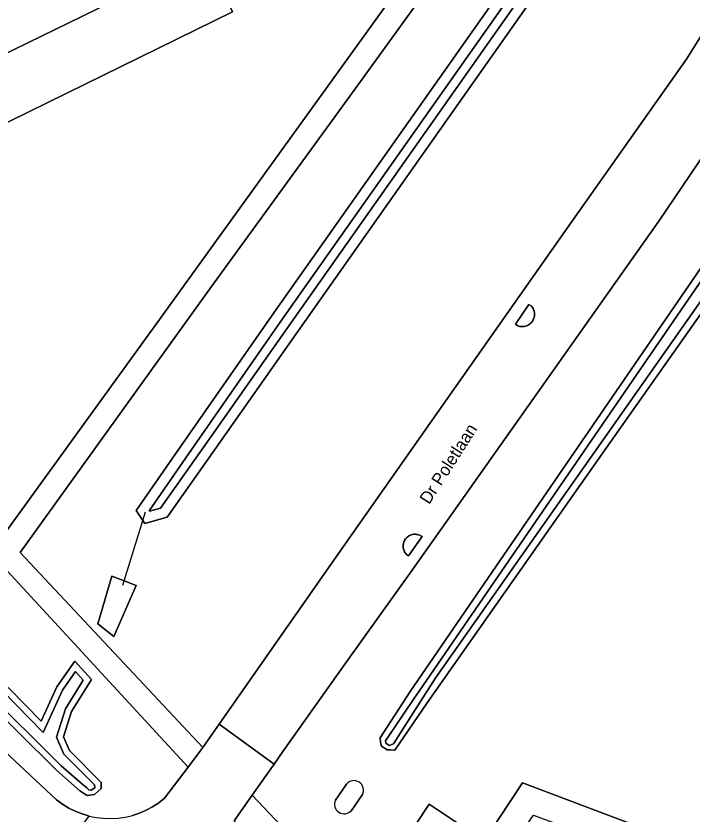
# Model space of a CAD drawing. Extents: x 158132 to 159664, y 385256 to 387218.
# Drawn here: x 159149 to 159204, y 386220.2 to 386285 of the extents above; entities that cross this region are included whole.
import ezdxf

# ---------------------------------------------------------------- set-up
doc = ezdxf.new("R2010")
doc.units = 0
for name, color, linetype in [('IMGEO_Berm_groen', 7, 'Continuous'), ('IMGEO_Duiker', 7, 'Continuous'), ('IMGEO_Groenvoorziening', 7, 'Continuous'), ('IMGEO_Oever', 7, 'Continuous'), ('IMGEO_Openbare_ruimte_label', 7, 'Continuous'), ('IMGEO_Pand', 7, 'Continuous'), ('IMGEO_Parkeervlak_open', 7, 'Continuous'), ('IMGEO_Rijbaan_lokaal_gesloten', 7, 'Continuous'), ('IMGEO_Rijbaan_lokaal_open', 7, 'Continuous'), ('IMGEO_Verkeerseiland_gesloten', 7, 'Continuous'), ('IMGEO_Voetpad_onverhard', 7, 'Continuous'), ('IMGEO_Voetpad_open', 7, 'Continuous'), ('IMGEO_Waterloop', 7, 'Continuous')]:
    doc.layers.add(name, color=color, linetype=linetype)

msp = doc.modelspace()

# ---------------------------------------------------------------- linework, layer by layer
at = {"layer": 'IMGEO_Berm_groen'}
for points in [[(159148.321, 386239.967), (159141.561, 386231.755), (159143.645, 386229.653), (159144.934, 386228.353), (159146.374, 386226.9), (159152.343, 386221.356), (159152.823, 386221.004), (159153.33, 386220.695), (159153.863, 386220.431), (159154.417, 386220.214), (159154.869, 386220.08), (159154.987, 386220.045), (159155.57, 386219.927), (159156.16, 386219.859), (159156.755, 386219.843), (159157.348, 386219.878), (159157.936, 386219.964), (159158.515, 386220.101), (159159.08, 386220.287), (159159.626, 386220.521), (159160.15, 386220.802), (159160.648, 386221.127), (159161.116, 386221.493), (159163.035, 386224.02)], [(159151.105, 386227.739), (159152.378, 386230.539), (159153.841, 386232.634), (159155.182, 386231.149), (159153.558, 386228.54), (159152.897, 386226.477), (159153.39, 386225.373), (159155.959, 386222.778), (159155.978, 386222.279), (159155.425, 386221.792), (159154.84, 386221.719), (159154.242, 386222.105), (159152.364, 386223.748), (159146.066, 386229.985), (159144.775, 386231.281), (159143.282, 386232.763), (159144.586, 386234.362), (159145.95, 386232.976), (159147.235, 386231.67)]]:
    msp.add_lwpolyline(points, close=True, dxfattribs=at)
at = {"layer": 'IMGEO_Duiker'}
msp.add_lwpolyline([(159157.726, 386238.808), (159157.834, 386239.159), (159159.345, 386244.053), (159159.564, 386244.761)], dxfattribs=at)
at = {"layer": 'IMGEO_Groenvoorziening'}
for points in [[(159108.848, 386282.056), (159117.567, 386273.343), (159130.648, 386260.403), (159140.343, 386250.704), (159148.101, 386242.94), (159161.049, 386260.864), (159173.188, 386277.68), (159184.907, 386293.934), (159196.39, 386309.759)], [(159148.09, 386301.717), (159150.98, 386295.609), (159151.929, 386296.073), (159159.646, 386299.844), (159161.883, 386295.226), (159164.449, 386289.929), (159166.651, 386285.382), (159145.544, 386275.043)], [(159189.781, 386297.34), (159177.033, 386279.71), (159164.932, 386263.075), (159149.388, 386241.446), (159164.231, 386225.621), (159165.558, 386227.517), (159175.438, 386241.635), (159184.786, 386254.949), (159194.152, 386268.251), (159203.536, 386281.54), (159205.023, 386283.901)], [(159208.814, 386279.502), (159201.285, 386268.363), (159181.095, 386239.838), (159175.909, 386232.566), (159170.744, 386225.279), (159170.034, 386224.271), (159168.243, 386221.728), (159180.772, 386208.483), (159190.199, 386222.736), (159197.505, 386219.987), (159205.272, 386217.087)], [(159197.068, 386250), (159182.45, 386229.237), (159179.829, 386225.403), (159179.44, 386225.427), (159179.21, 386225.427), (159178.75, 386225.731), (159178.657, 386226.01), (159178.628, 386226.397), (159181.071, 386230.164), (159194.698, 386250), (159210.611, 386273.163)], [(159212.538, 386271.974), (159197.068, 386250)], [(159175.011, 386221.343), (159175.899, 386222.625)], [(159177.205, 386221.788), (159176.302, 386220.505)]]:
    msp.add_lwpolyline(points, dxfattribs=at)
for points in [[(159165.33, 386250), (159161.327, 386244.313), (159159.507, 386243.797), (159159.345, 386244.053), (159158.827, 386244.873), (159162.396, 386250), (159170.003, 386260.929), (159189.652, 386288.81), (159201.189, 386305.946), (159202.72, 386305.624), (159203.385, 386304.266), (159200.668, 386299.926), (159191.667, 386287.402), (159171.809, 386259.206)], [(159157.834, 386239.159), (159158.827, 386238.782), (159157.008, 386234.643), (159155.686, 386235.656), (159156.837, 386239.538)], [(159185.717, 386218.949), (159182.602, 386214.246), (159179.494, 386216.305), (159182.61, 386221.008)]]:
    msp.add_lwpolyline(points, close=True, dxfattribs=at)
for centre, radius, start, end in [((159176.509, 386222.139), 0.78, 333.26024, 141.4291), ((159175.705, 386220.999), 0.775, 153.612, 320.41205)]:
    msp.add_arc(centre, radius, start, end, dxfattribs=at)
at = {"layer": 'IMGEO_Oever'}
for points in [[(159165.33, 386250), (159171.809, 386259.206), (159191.667, 386287.402), (159200.668, 386299.926), (159203.385, 386304.266), (159202.72, 386305.624), (159201.189, 386305.946), (159189.652, 386288.81), (159170.003, 386260.929), (159162.396, 386250), (159158.827, 386244.873), (159159.345, 386244.053), (159159.507, 386243.797), (159161.327, 386244.313)], [(159159.89, 386244.799), (159159.858, 386244.85), (159163.101, 386249.509), (159170.707, 386260.436), (159190.36, 386288.322), (159201.579, 386304.986), (159202.133, 386304.869), (159202.403, 386304.317), (159199.954, 386300.405), (159190.967, 386287.9), (159171.106, 386259.701), (159164.627, 386250.495), (159160.8, 386245.057)], [(159183.171, 386231.298), (159181.865, 386229.262), (159179.734, 386225.903), (159179.373, 386225.783), (159179.112, 386225.964), (159179.072, 386226.165), (159181.368, 386229.571), (159182.116, 386230.631), (159195.19, 386249.662), (159209.402, 386270.349), (159211.086, 386272.8), (159212.582, 386274.684), (159213.949, 386276.664), (159215.181, 386278.731), (159217.39, 386282.163), (159218.099, 386281.868), (159218.484, 386281.665), (159216.829, 386279.174), (159215.433, 386276.77), (159213.843, 386274.489), (159212.07, 386272.347), (159196.58, 386250.344)], [(159153.841, 386232.634), (159152.378, 386230.539), (159151.105, 386227.739), (159147.235, 386231.67), (159145.95, 386232.976), (159144.586, 386234.362), (159143.282, 386232.763), (159144.775, 386231.281), (159146.066, 386229.985), (159152.364, 386223.748), (159154.242, 386222.105), (159154.84, 386221.719), (159155.425, 386221.792), (159155.978, 386222.279), (159155.959, 386222.778), (159153.39, 386225.373), (159152.897, 386226.477), (159153.558, 386228.54), (159155.182, 386231.149)], [(159155.016, 386222.977), (159155.433, 386222.572), (159155.458, 386222.344), (159155.165, 386222.141), (159154.969, 386222.173), (159154.798, 386222.323), (159154.348, 386222.716), (159152.725, 386224.136), (159146.44, 386230.36), (159145.149, 386231.656), (159143.996, 386232.801), (159144.623, 386233.569), (159145.572, 386232.604), (159146.857, 386231.298), (159151.268, 386226.818), (159152.84, 386230.275), (159153.894, 386231.785), (159154.521, 386231.09), (159153.073, 386228.764), (159152.331, 386226.446), (159152.946, 386225.069)]]:
    msp.add_lwpolyline(points, close=True, dxfattribs=at)
msp.add_lwpolyline([(159210.611, 386273.163), (159194.698, 386250), (159181.071, 386230.164), (159178.628, 386226.397), (159178.657, 386226.01), (159178.75, 386225.731), (159179.21, 386225.427), (159179.44, 386225.427), (159179.829, 386225.403), (159182.45, 386229.237), (159197.068, 386250), (159212.538, 386271.974)], dxfattribs=at)
at = {"layer": 'IMGEO_Pand'}
msp.add_lwpolyline([(159179.494, 386216.305), (159182.602, 386214.246), (159185.717, 386218.949), (159182.61, 386221.008)], close=True, dxfattribs=at)
at = {"layer": 'IMGEO_Parkeervlak_open'}
msp.add_lwpolyline([(159166.651, 386285.382), (159164.449, 386289.929), (159143.317, 386279.598), (159145.544, 386275.043)], close=True, dxfattribs=at)
at = {"layer": 'IMGEO_Rijbaan_lokaal_gesloten'}
for points in [[(159205.023, 386283.901), (159203.536, 386281.54), (159194.152, 386268.251), (159184.786, 386254.949), (159175.438, 386241.635), (159165.558, 386227.517), (159170.034, 386224.271), (159170.744, 386225.279), (159175.909, 386232.566), (159181.095, 386239.838), (159201.285, 386268.363), (159208.814, 386279.502)], [(159166.788, 386219.661), (159168.243, 386221.728), (159170.034, 386224.271), (159165.558, 386227.517), (159164.231, 386225.621), (159163.995, 386225.283), (159163.035, 386224.02), (159161.116, 386221.493), (159160.648, 386221.127), (159160.15, 386220.802), (159159.626, 386220.521), (159159.08, 386220.287), (159158.515, 386220.101)]]:
    msp.add_lwpolyline(points, dxfattribs=at)
for points in [[(159103.443, 386270.199), (159100.086, 386266.87), (159110, 386256.994), (159112.16, 386254.95), (159117.045, 386250), (159126.165, 386240.758), (159143.275, 386223.438), (159148.706, 386217.941), (159150.875, 386216.144), (159151.525, 386215.482), (159154.987, 386220.045), (159154.869, 386220.08), (159154.417, 386220.214), (159153.863, 386220.431), (159153.33, 386220.695), (159152.823, 386221.004), (159152.343, 386221.356), (159146.374, 386226.9), (159144.934, 386228.353), (159143.645, 386229.653), (159141.561, 386231.755), (159140, 386233.33), (159129.471, 386243.952), (159123.473, 386250)], [(159189.82, 386259.862), (159189.624, 386259.996), (159190.713, 386261.599), (159190.914, 386261.496), (159190.972, 386261.427), (159191.023, 386261.353), (159191.067, 386261.275), (159191.104, 386261.194), (159191.134, 386261.109), (159191.157, 386261.022), (159191.171, 386260.934), (159191.178, 386260.844), (159191.177, 386260.755), (159191.168, 386260.665), (159191.151, 386260.577), (159191.126, 386260.491), (159191.094, 386260.407), (159191.054, 386260.327), (159191.008, 386260.25), (159190.954, 386260.178), (159190.895, 386260.111), (159190.83, 386260.049), (159190.76, 386259.993), (159190.685, 386259.944), (159190.606, 386259.901), (159190.523, 386259.866), (159190.438, 386259.838), (159190.351, 386259.818), (159190.262, 386259.806), (159190.172, 386259.801), (159190.083, 386259.804), (159189.994, 386259.816), (159189.906, 386259.835)], [(159180.769, 386241.301), (159180.713, 386241.365), (159180.663, 386241.434), (159180.618, 386241.507), (159180.581, 386241.584), (159180.551, 386241.664), (159180.527, 386241.746), (159180.511, 386241.83), (159180.502, 386241.915), (159180.501, 386242), (159180.508, 386242.085), (159180.522, 386242.169), (159180.543, 386242.252), (159180.571, 386242.333), (159180.607, 386242.41), (159180.649, 386242.484), (159180.698, 386242.555), (159180.752, 386242.62), (159180.812, 386242.681), (159180.877, 386242.736), (159180.947, 386242.785), (159181.021, 386242.828), (159181.098, 386242.864), (159181.179, 386242.894), (159181.261, 386242.916), (159181.345, 386242.93), (159181.43, 386242.937), (159181.516, 386242.937), (159181.601, 386242.929), (159181.685, 386242.914), (159181.767, 386242.891), (159181.847, 386242.861), (159182.046, 386242.754), (159180.95, 386241.191)]]:
    msp.add_lwpolyline(points, close=True, dxfattribs=at)
at = {"layer": 'IMGEO_Rijbaan_lokaal_open'}
msp.add_lwpolyline([(159164.449, 386289.929), (159161.883, 386295.226), (159154.152, 386291.482), (159151.929, 386296.073), (159150.98, 386295.609), (159148.09, 386301.717), (159148.667, 386303.059), (159147.686, 386302.57), (159143.713, 386300.59), (159142.345, 386299.908), (159143.804, 386299.576), (159146.826, 386293.504), (159146.258, 386293.231), (159148.444, 386288.717), (159140.694, 386284.963), (159143.317, 386279.598)], close=True, dxfattribs=at)
at = {"layer": 'IMGEO_Verkeerseiland_gesloten'}
for points in [[(159189.82, 386259.862), (159189.906, 386259.835), (159189.994, 386259.816), (159190.083, 386259.804), (159190.172, 386259.801), (159190.262, 386259.806), (159190.351, 386259.818), (159190.438, 386259.838), (159190.523, 386259.866), (159190.606, 386259.901), (159190.685, 386259.944), (159190.76, 386259.993), (159190.83, 386260.049), (159190.895, 386260.111), (159190.954, 386260.178), (159191.008, 386260.25), (159191.054, 386260.327), (159191.094, 386260.407), (159191.126, 386260.491), (159191.151, 386260.577), (159191.168, 386260.665), (159191.177, 386260.755), (159191.178, 386260.844), (159191.171, 386260.934), (159191.157, 386261.022), (159191.134, 386261.109), (159191.104, 386261.194), (159191.067, 386261.275), (159191.023, 386261.353), (159190.972, 386261.427), (159190.914, 386261.496), (159190.713, 386261.599), (159189.624, 386259.996)], [(159180.769, 386241.301), (159180.95, 386241.191), (159182.046, 386242.754), (159181.847, 386242.861), (159181.767, 386242.891), (159181.685, 386242.914), (159181.601, 386242.929), (159181.516, 386242.937), (159181.43, 386242.937), (159181.345, 386242.93), (159181.261, 386242.916), (159181.179, 386242.894), (159181.098, 386242.864), (159181.021, 386242.828), (159180.947, 386242.785), (159180.877, 386242.736), (159180.812, 386242.681), (159180.752, 386242.62), (159180.698, 386242.555), (159180.649, 386242.484), (159180.607, 386242.41), (159180.571, 386242.333), (159180.543, 386242.252), (159180.522, 386242.169), (159180.508, 386242.085), (159180.501, 386242), (159180.502, 386241.915), (159180.511, 386241.83), (159180.527, 386241.746), (159180.551, 386241.664), (159180.581, 386241.584), (159180.618, 386241.507), (159180.663, 386241.434), (159180.713, 386241.365)]]:
    msp.add_lwpolyline(points, close=True, dxfattribs=at)
at = {"layer": 'IMGEO_Voetpad_onverhard'}
msp.add_lwpolyline([(159205.272, 386217.087), (159197.505, 386219.987), (159190.199, 386222.736), (159180.772, 386208.483), (159182.075, 386207.106), (159191.095, 386220.106), (159196.938, 386217.937), (159198.295, 386217.434), (159197.151, 386215.754), (159197.439, 386215.547), (159190.442, 386205.802), (159190.397, 386205.834), (159189.358, 386204.308), (159208.99, 386183.638)], dxfattribs=at)
at = {"layer": 'IMGEO_Voetpad_open'}
for points in [[(159148.321, 386239.967), (159163.035, 386224.02), (159163.995, 386225.283), (159164.231, 386225.621), (159149.388, 386241.446), (159164.932, 386263.075), (159177.033, 386279.71), (159189.781, 386297.34)], [(159184.907, 386293.934), (159173.188, 386277.68), (159161.049, 386260.864), (159148.101, 386242.94)]]:
    msp.add_lwpolyline(points, dxfattribs=at)
msp.add_lwpolyline([(159185.76, 386203.211), (159182.075, 386207.106), (159180.772, 386208.483), (159168.243, 386221.728), (159166.788, 386219.661), (159186.562, 386198.75), (159201.246, 386183.411), (159211.636, 386172.54), (159214.832, 386169.196), (159216.623, 386171.01), (159213.479, 386173.941), (159213.299, 386174.131)], close=True, dxfattribs=at)
at = {"layer": 'IMGEO_Waterloop'}
for points in [[(159159.89, 386244.799), (159160.8, 386245.057), (159164.627, 386250.495), (159171.106, 386259.701), (159190.967, 386287.9), (159199.954, 386300.405), (159202.403, 386304.317), (159202.133, 386304.869), (159201.579, 386304.986), (159190.36, 386288.322), (159170.707, 386260.436), (159163.101, 386249.509), (159159.858, 386244.85)], [(159183.171, 386231.298), (159196.58, 386250.344), (159212.07, 386272.347), (159213.843, 386274.489), (159215.433, 386276.77), (159216.829, 386279.174), (159218.484, 386281.665), (159218.099, 386281.868), (159217.39, 386282.163), (159215.181, 386278.731), (159213.949, 386276.664), (159212.582, 386274.684), (159211.086, 386272.8), (159209.402, 386270.349), (159195.19, 386249.662), (159182.116, 386230.631), (159181.368, 386229.571), (159179.072, 386226.165), (159179.112, 386225.964), (159179.373, 386225.783), (159179.734, 386225.903), (159181.865, 386229.262)], [(159157.834, 386239.159), (159156.837, 386239.538), (159155.686, 386235.656), (159157.008, 386234.643), (159158.827, 386238.782)], [(159155.016, 386222.977), (159152.946, 386225.069), (159152.331, 386226.446), (159153.073, 386228.764), (159154.521, 386231.09), (159153.894, 386231.785), (159152.84, 386230.275), (159151.268, 386226.818), (159146.857, 386231.298), (159145.572, 386232.604), (159144.623, 386233.569), (159143.996, 386232.801), (159145.149, 386231.656), (159146.44, 386230.36), (159152.725, 386224.136), (159154.348, 386222.716), (159154.798, 386222.323), (159154.969, 386222.173), (159155.165, 386222.141), (159155.458, 386222.344), (159155.433, 386222.572)]]:
    msp.add_lwpolyline(points, close=True, dxfattribs=at)
for points in [[(159175.899, 386222.625), (159175.011, 386221.343)], [(159176.302, 386220.505), (159177.205, 386221.788)]]:
    msp.add_lwpolyline(points, dxfattribs=at)
for centre, radius, start, end in [((159176.509, 386222.139), 0.78, 333.26024, 141.4291), ((159175.705, 386220.999), 0.775, 153.612, 320.41205)]:
    msp.add_arc(centre, radius, start, end, dxfattribs=at)

# ---------------------------------------------------------------- texts
at = {"layer": 'IMGEO_Openbare_ruimte_label'}
msp.add_text('Dr Poletlaan', height=1, rotation=57.45411, dxfattribs=at).set_placement((159182.618, 386245.3))

doc.saveas('drawing.dxf')
